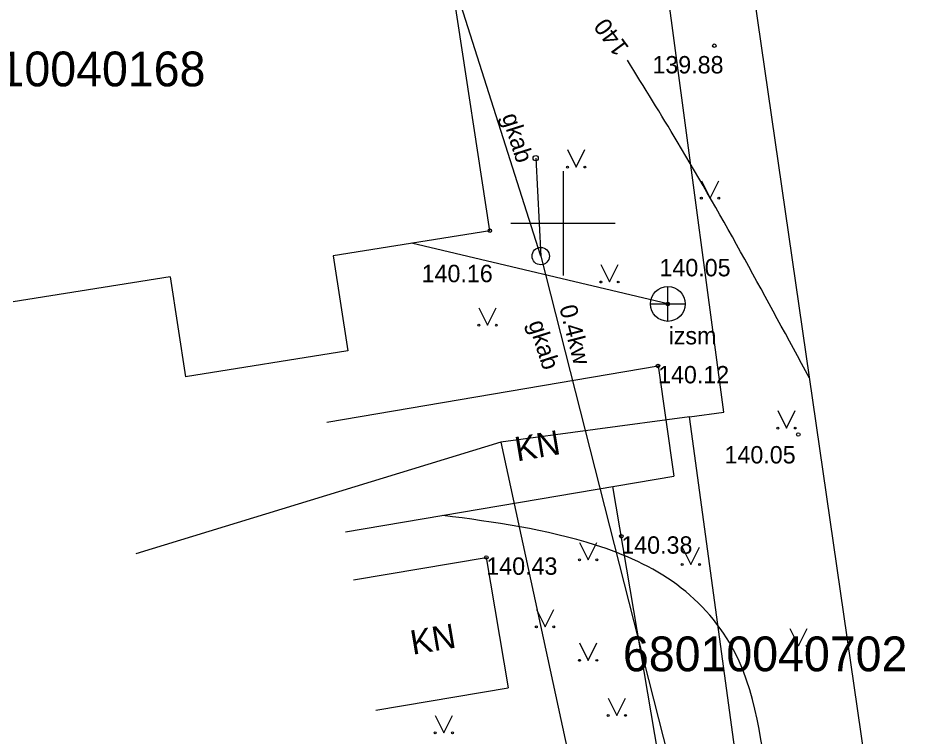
# Model space of a CAD drawing. Extents: x 728848 to 728956, y 273098 to 273185.
# Drawn here: x 728884.32 to 728910.04, y 273135.25 to 273155.9 of the extents above; entities that cross this region are included whole.
import ezdxf

# ---------------------------------------------------------------- set-up
doc = ezdxf.new("R2010")
doc.units = 0
for name, color, linetype in [('BUVE_EKAS_####_####_#', 7, 'Continuous'), ('BUVE_EKAS_RAKS_TKST_#', 7, 'Continuous'), ('ELEK_ELEM_####_####_#', 7, 'Continuous'), ('ELEK_SAIT_####_####_#', 7, 'Continuous'), ('ELEK_VADV_ZSPR_####_#', 7, 'Continuous'), ('ELEK_VADV_ZSPR_TKST_#', 7, 'Continuous'), ('GEOD_ELEM_####_####_#', 7, 'Continuous'), ('NORB_ZOGS_ZSTP_####_#', 7, 'Continuous'), ('RELJ_AATZ_####_TKST_#', 7, 'Continuous'), ('RELJ_ELEM_####_####_#', 7, 'Continuous'), ('RELJ_HORZ_####_TKST_#', 7, 'Continuous'), ('RELJ_HORZ_PAMT_####_#', 7, 'Continuous'), ('RELJ_HORZ_RESN_####_#', 7, 'Continuous'), ('ROBZ_KADS_####_TKST_#', 7, 'Continuous'), ('ROBZ_UZMR_####_####_#', 7, 'Continuous'), ('SKAN_ELEM_####_####_#', 7, 'Continuous'), ('SKAN_ELEM_PAST_TKST_#', 7, 'Continuous'), ('SKAN_VADP_PAST_####_#', 7, 'Continuous'), ('TERT_ELEM_####_####_#', 7, 'Continuous')]:
    doc.layers.add(name, color=color, linetype=linetype)

msp = doc.modelspace()

# ---------------------------------------------------------------- linework, layer by layer
at = {"layer": 'BUVE_EKAS_####_####_#'}
for p, q in [((728897.893, 273149.784), (728895.607, 273164.692)), ((728904.348, 273164.427), (728910.037, 273125.181)), ((728897.893, 273149.784), (728893.382, 273149.063)), ((728893.382, 273149.063), (728893.807, 273146.327)), ((728888.697, 273148.457), (728884.187, 273147.736)), ((728888.697, 273148.457), (728889.144, 273145.582)), ((728893.807, 273146.327), (728889.144, 273145.582)), ((728893.205, 273144.28), (728902.73, 273145.895)), ((728902.73, 273145.895), (728903.188, 273142.727)), ((728893.74, 273141.125), (728903.188, 273142.727)), ((728893.974, 273139.745), (728897.791, 273140.392)), ((728897.791, 273140.392), (728898.422, 273136.645)), ((728894.609, 273135.998), (728898.422, 273136.645))]:
    msp.add_line(p, q, dxfattribs=at)
at = {"layer": 'ELEK_ELEM_####_####_#'}
for centre, radius in [((728899.212, 273151.869), 0.075), ((728899.357, 273149.053), 0.25)]:
    msp.add_circle(centre, radius, dxfattribs=at)
at = {"layer": 'ELEK_SAIT_####_####_#'}
msp.add_line((728899.212, 273151.869), (728899.357, 273149.053), dxfattribs=at)
at = {"layer": 'ELEK_VADV_ZSPR_####_#'}
for q in [(728896.751, 273157.234), (728905.113, 273126.437)]:
    msp.add_line((728899.357, 273149.053), q, dxfattribs=at)
at = {"layer": 'GEOD_ELEM_####_####_#'}
for p, q in [((728900, 273151.5), (728900, 273150)), ((728898.5, 273150), (728900, 273150)), ((728900, 273150), (728900, 273148.5)), ((728900, 273150), (728901.5, 273150))]:
    msp.add_line(p, q, dxfattribs=at)
at = {"layer": 'NORB_ZOGS_ZSTP_####_#'}
msp.add_lwpolyline([(728904.34, 273125.23), (728901.425, 273142.428)], dxfattribs=at)
at = {"layer": 'RELJ_ELEM_####_####_#'}
for centre in [(728904.348, 273155.102), (728897.893, 273149.784), (728903.013, 273147.678), (728902.73, 273145.895), (728906.764, 273143.925), (728901.673, 273140.998), (728897.791, 273140.392)]:
    msp.add_circle(centre, 0.05, dxfattribs=at)
at = {"layer": 'RELJ_HORZ_PAMT_####_#'}
msp.add_spline([(728907.225, 273122.736), (728908.147, 273125.08), (728908.147, 273127.137), (728906.094, 273133.127), (728904.941, 273137.666), (728903.27, 273139.609), (728900.929, 273140.747), (728896.538, 273141.6)], degree=3, dxfattribs=at)
at = {"layer": 'RELJ_HORZ_RESN_####_#'}
msp.add_spline([(728907.086, 273145.54), (728903.284, 273152.345), (728901.849, 273154.685)], degree=3, dxfattribs=at)
at = {"layer": 'ROBZ_UZMR_####_####_#'}
for points in [[(728902.844, 273122.265), (728906.58, 273122.86), (728903.634, 273144.437), (728904.623, 273144.571), (728901.876, 273165.08), (728895.601, 273164.553)], [(728903.634, 273144.437), (728898.213, 273143.701), (728902.844, 273122.265), (728888.555, 273119.835)], [(728898.213, 273143.701), (728887.709, 273140.492)]]:
    msp.add_lwpolyline(points, dxfattribs=at)
at = {"layer": 'SKAN_ELEM_####_####_#'}
for p, q in [((728903.013, 273147.178), (728903.013, 273148.178)), ((728902.513, 273147.678), (728903.513, 273147.678))]:
    msp.add_line(p, q, dxfattribs=at)
msp.add_circle((728903.013, 273147.678), 0.5, dxfattribs=at)
at = {"layer": 'SKAN_VADP_PAST_####_#'}
msp.add_lwpolyline([(728903.013, 273147.678), (728895.638, 273149.424)], dxfattribs=at)
at = {"layer": 'TERT_ELEM_####_####_#'}
for p, q in [((728900.124, 273152.114), (728900.374, 273151.614)), ((728900.374, 273151.614), (728900.624, 273152.114)), ((728903.976, 273151.219), (728904.226, 273150.719)), ((728904.226, 273150.719), (728904.476, 273151.219)), ((728901.087, 273148.81), (728901.337, 273148.31)), ((728901.337, 273148.31), (728901.587, 273148.81)), ((728897.579, 273147.571), (728897.829, 273147.071)), ((728897.829, 273147.071), (728898.079, 273147.571)), ((728906.177, 273144.611), (728906.427, 273144.111)), ((728906.427, 273144.111), (728906.677, 273144.611)), ((728900.468, 273140.825), (728900.718, 273140.325)), ((728900.718, 273140.325), (728900.968, 273140.825)), ((728903.425, 273140.687), (728903.675, 273140.187)), ((728903.675, 273140.187), (728903.925, 273140.687)), ((728899.23, 273138.897), (728899.48, 273138.397)), ((728899.48, 273138.397), (728899.73, 273138.897)), ((728906.52, 273138.346), (728906.77, 273137.846)), ((728906.77, 273137.846), (728907.02, 273138.346)), ((728900.468, 273137.933), (728900.718, 273137.433)), ((728900.718, 273137.433), (728900.968, 273137.933)), ((728901.293, 273136.35), (728901.543, 273135.85)), ((728901.543, 273135.85), (728901.793, 273136.35)), ((728896.319, 273135.847), (728896.569, 273135.347)), ((728896.569, 273135.347), (728896.819, 273135.847))]:
    msp.add_line(p, q, dxfattribs=at)
for centre, radius in [((728900.124, 273151.614), 0.028), ((728900.624, 273151.614), 0.0263), ((728903.975, 273150.719), 0.028), ((728904.475, 273150.719), 0.0263), ((728901.087, 273148.309), 0.028), ((728901.587, 273148.309), 0.0263), ((728897.579, 273147.07), 0.028), ((728898.079, 273147.07), 0.0263), ((728906.176, 273144.11), 0.028), ((728906.676, 273144.11), 0.0263), ((728900.468, 273140.324), 0.028), ((728900.968, 273140.324), 0.0263), ((728903.425, 273140.186), 0.028), ((728903.925, 273140.186), 0.0263), ((728899.23, 273138.397), 0.028), ((728899.73, 273138.397), 0.0263), ((728906.52, 273137.846), 0.028), ((728907.02, 273137.846), 0.0263), ((728900.468, 273137.433), 0.028), ((728900.968, 273137.433), 0.0263), ((728901.293, 273135.85), 0.028), ((728901.793, 273135.85), 0.0263), ((728896.319, 273135.347), 0.028), ((728896.819, 273135.347), 0.0263)]:
    msp.add_circle(centre, radius, dxfattribs=at)

# ---------------------------------------------------------------- texts
at = {"layer": 'BUVE_EKAS_RAKS_TKST_#'}
for p in [(728898.677, 273143.15), (728895.672, 273137.59)]:
    msp.add_text('KN', height=0.7, rotation=9.62, dxfattribs=at).set_placement(p)
at = {"layer": 'ELEK_VADV_ZSPR_TKST_#'}
for s, rotation, p in [('gkab', 287.6743, (728898.233, 273153.076)), ('0.4kw', 284.278, (728899.887, 273147.583)), ('gkab', 287.6743, (728898.995, 273147.126))]:
    msp.add_text(s, height=0.5, rotation=rotation, dxfattribs=at).set_placement(p)
at = {"layer": 'RELJ_AATZ_####_TKST_#'}
for s, p in [('139.88', (728902.568, 273154.305)), ('140.16', (728895.931, 273148.304)), ('140.12', (728902.73, 273145.395)), ('140.05', (728904.642, 273143.093)), ('140.38', (728901.673, 273140.498)), ('140.43', (728897.791, 273139.892))]:
    msp.add_text(s, height=0.5, dxfattribs=at).set_placement(p)
at = {"layer": 'RELJ_HORZ_####_TKST_#'}
msp.add_text('140', height=0.5, rotation=126.3292, dxfattribs=at).set_placement((728901.914, 273155.043))
at = {"layer": 'ROBZ_KADS_####_TKST_#'}
for s, p in [('68010040168', (728881.532, 273153.934)), ('68010040702', (728901.72, 273137.119))]:
    msp.add_text(s, height=1, dxfattribs=at).set_placement(p)
at = {"layer": 'SKAN_ELEM_PAST_TKST_#'}
for s, p in [('140.05', (728902.771, 273148.472)), ('izsm', (728903.034, 273146.516))]:
    msp.add_text(s, height=0.5, dxfattribs=at).set_placement(p)

doc.saveas('drawing.dxf')
